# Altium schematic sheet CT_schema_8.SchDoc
size 308 x 210 mm
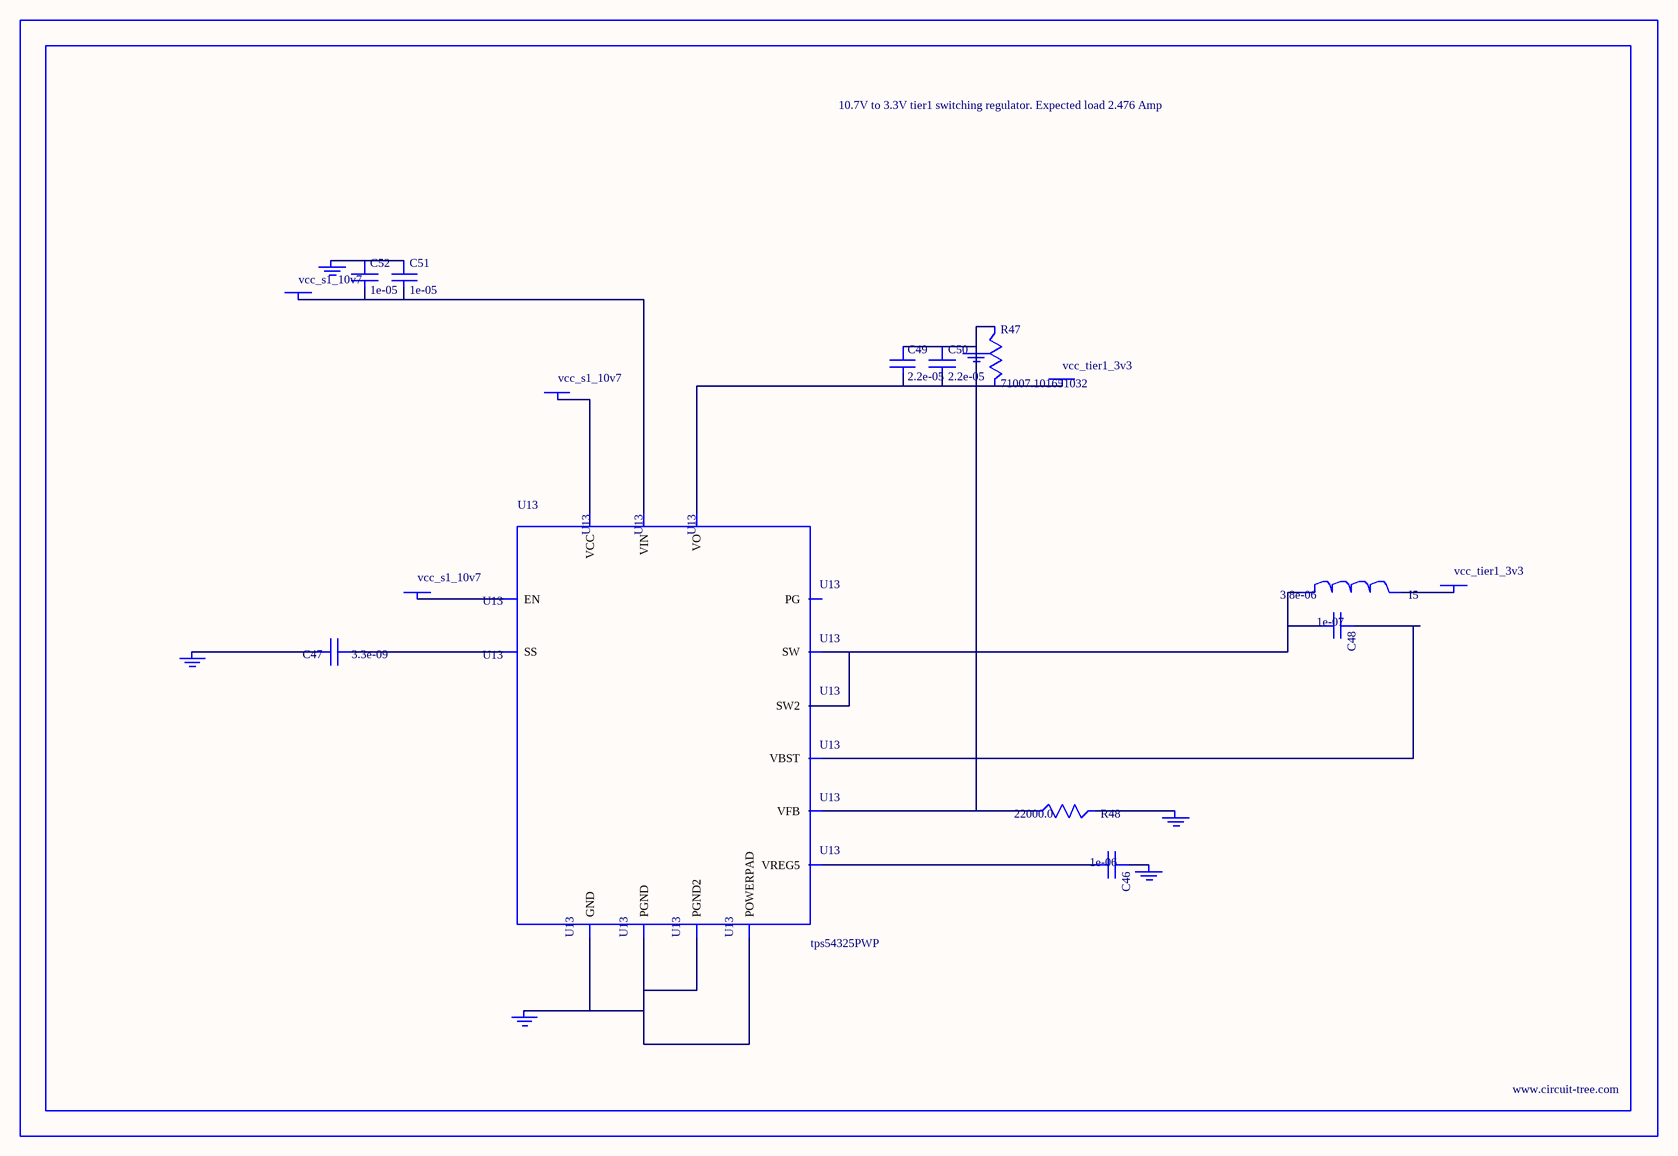
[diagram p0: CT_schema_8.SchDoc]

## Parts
BORDER7  (no value)
C46  1e-06  [C0603]
C47  3.3e-09  [C0402]
C48  1e-07  [C0402]
C49  2.2e-05  [C1210]
C50  2.2e-05  [C1210]
C51  1e-05  [C1206]
C52  1e-05  [C1206]
GND_INSTANCE_7_0  (no value)
GND_INSTANCE_7_1  (no value)
GND_INSTANCE_7_2  (no value)
GND_INSTANCE_7_3  (no value)
GND_INSTANCE_7_4  (no value)
GND_INSTANCE_7_5  (no value)
I5  3.8e-06  [DR1040]
POWER_INSTANCE_7_0  vcc_tier1_3v3
POWER_INSTANCE_7_1  vcc_s1_10v7
POWER_INSTANCE_7_2  vcc_tier1_3v3
POWER_INSTANCE_7_3  vcc_s1_10v7
POWER_INSTANCE_7_4  vcc_s1_10v7
R47  71007.101651032  [R0603]
R48  22000.0  [R0603]
U13  tps54325PWP  [HTSSOP14]

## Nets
NetC46_1: C46.1 GND_INSTANCE_7_2.0(GND)
NetC46_2: C46.2 U13.3(VREG5)
NetC47_1: C47.1 U13.4(SS)
NetC47_2: C47.2 GND_INSTANCE_7_3.0(GND)
NetC48_1: C48.1 U13.12(VBST)
NetC48_2: C48.2 I5.1 U13.10(SW) U13.11(SW2)
NetC49_1: C49.1 C50.1 GND_INSTANCE_7_0.0(GND) R47.1 R48.1 U13.2(VFB)
NetC49_2: C49.2 C50.2 POWER_INSTANCE_7_0.0(PWR) R47.2 U13.1(VO)
NetC51_1: C51.1 C52.1 GND_INSTANCE_7_5.0(GND)
NetC51_2: C51.2 C52.2 POWER_INSTANCE_7_3.0(PWR) U13.13(VIN)
NetGND_INSTANCE_7_1_0: GND_INSTANCE_7_1.0(GND) R48.2
NetGND_INSTANCE_7_4_0: GND_INSTANCE_7_4.0(GND) U13.5(GND) U13.8(PGND) U13.9(PGND2) U13.15(POWERPAD)
NetI5_2: I5.2 POWER_INSTANCE_7_2.0(PWR)
NetPOWER_INSTANCE_7_1_0: POWER_INSTANCE_7_1.0(PWR) U13.7(EN)
NetPOWER_INSTANCE_7_4_0: POWER_INSTANCE_7_4.0(PWR) U13.14(VCC)

Not connected (* = marked no-connect by the designer): U13 6(PG)

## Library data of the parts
BORDER7 = BORDER_PAGE7
C46 = C0603C105K3RACTU
C47 = C0402C332K3RAC
C48 = C0402C104K3RACTU
C49 C50 = GRM32ER61E226ME15L
C51 C52 = C1206C106K3RACTU
GND_INSTANCE_7_0-GND_INSTANCE_7_5 = GND
I5 = DR1040-3R8-R
POWER_INSTANCE_7_0-POWER_INSTANCE_7_4 = PWR
R47 = R47
R48 = RC0603JR-0722KL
